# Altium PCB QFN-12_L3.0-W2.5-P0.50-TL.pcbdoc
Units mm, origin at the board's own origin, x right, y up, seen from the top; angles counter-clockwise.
Board outline 16.25 x 16.27 mm, 2 copper layers (Top Layer, Bottom Layer), stack 0 mm thick; 1 components, 0 nets, 12 pads, 0 vias.
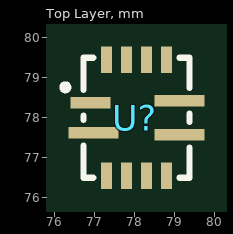
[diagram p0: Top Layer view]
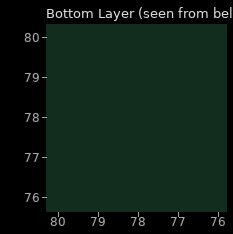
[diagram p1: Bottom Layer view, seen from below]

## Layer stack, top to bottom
Top Layer: signal copper (thickness not stored)
Bottom Layer: signal copper (thickness not stored)

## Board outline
86.103,69.85 69.85,69.85 69.85,86.115 86.103,86.115

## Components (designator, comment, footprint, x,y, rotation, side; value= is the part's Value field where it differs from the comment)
U? "" QFN-12_L3.0-W2.5-P0.50-TL 78.016,77.983 r0 top

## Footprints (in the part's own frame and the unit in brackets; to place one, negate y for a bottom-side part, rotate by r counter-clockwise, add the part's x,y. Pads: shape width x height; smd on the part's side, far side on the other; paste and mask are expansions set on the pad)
QFN-12_L3.0-W2.5-P0.50-TL [mm]
  rect 1x0.28 smd: 1(-1.113,0.375)
  rect 1.25x0.28 smd: 2(-1.038,-0.375) 7(1.113,-0.425) 8(1.113,0.425)
  rect 0.28x0.665 smd: 3(-0.713,-1.45) 4(-0.213,-1.45) 5(0.287,-1.45) 6(0.787,-1.45) 9(0.787,1.45) 10(0.287,1.45) 11(-0.213,1.45) 12(-0.713,1.45)
  silkscreen extent -1.82,-1.5 1.36,1.5

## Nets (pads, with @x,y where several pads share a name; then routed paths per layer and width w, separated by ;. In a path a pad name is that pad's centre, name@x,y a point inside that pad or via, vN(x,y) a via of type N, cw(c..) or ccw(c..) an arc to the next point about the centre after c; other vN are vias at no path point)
pads on no net: U?.1 U?.2 U?.3 U?.4 U?.5 U?.6 U?.7 U?.8 U?.9 U?.10 U?.11 U?.12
